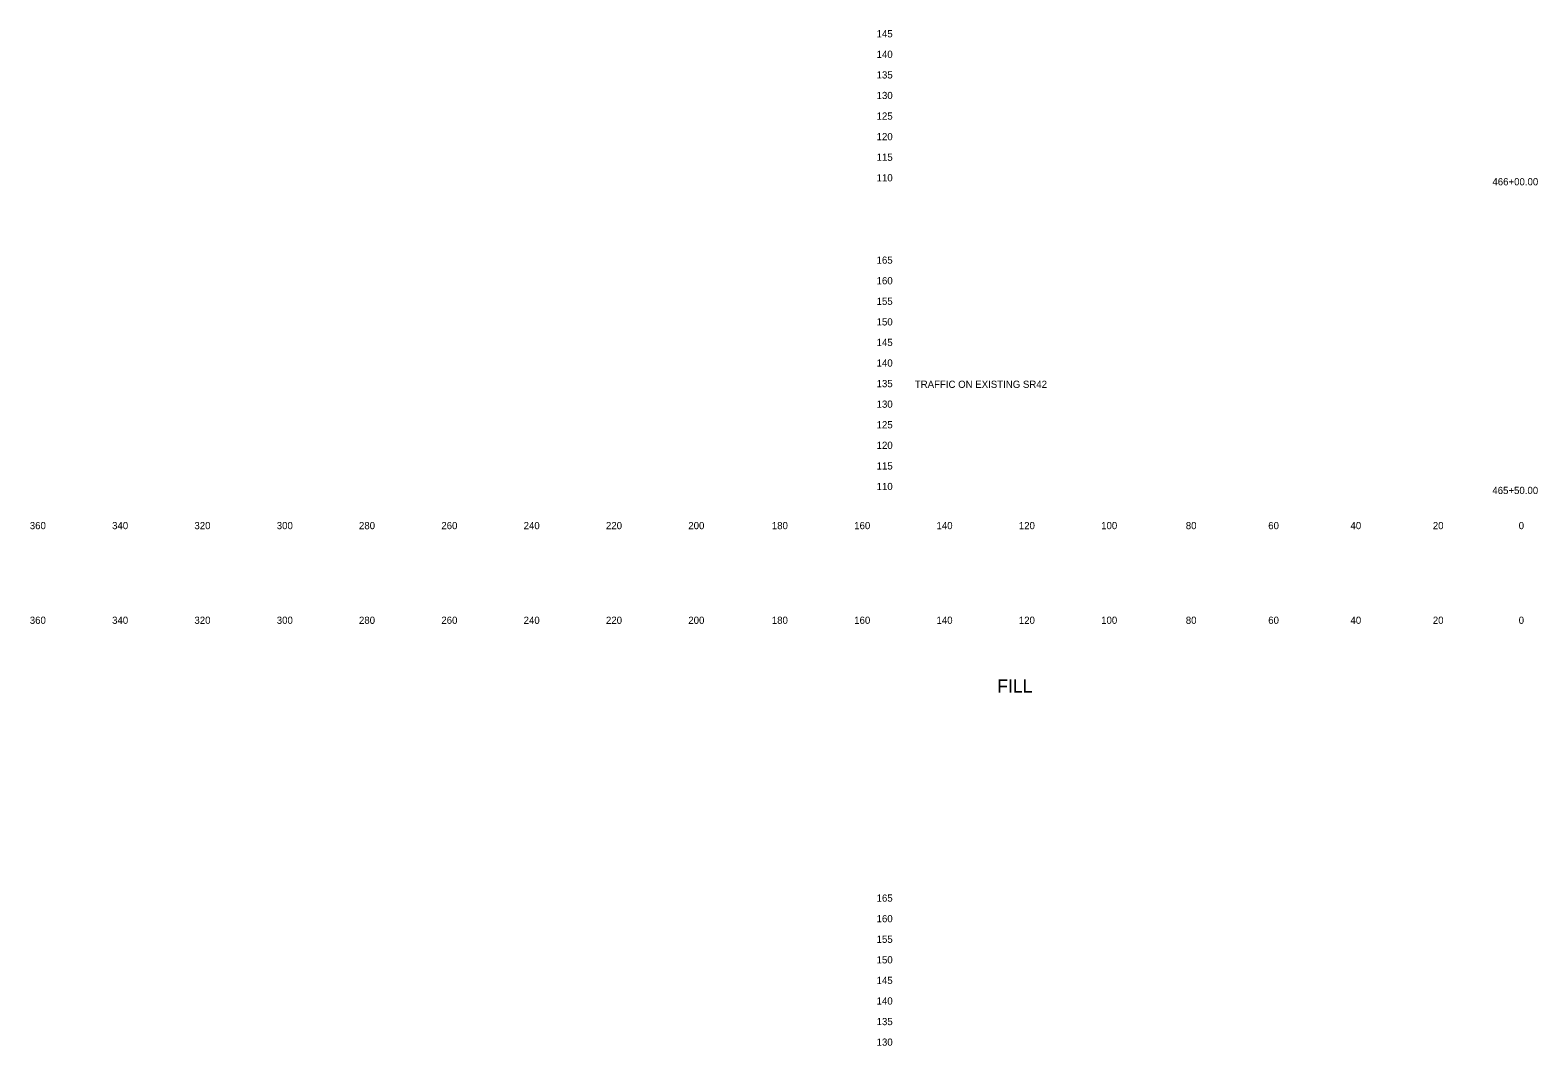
# Model space of a CAD drawing. Extents: x 21281 to 22024, y 6472 to 15198.
# Drawn here: x 21280.5 to 21646.8, y 8649.8 to 8896.6 of the extents above; entities that cross this region are included whole.
import ezdxf

# ---------------------------------------------------------------- set-up
doc = ezdxf.new("R2010")
doc.units = 0
for name, color, linetype in [('XS_SHEET_LABELS_ELEVATION', 7, 'Continuous'), ('XS_SHEET_LABELS_OFFSET', 7, 'Continuous'), ('XS_SHEET_LABELS_STATION', 7, 'Continuous')]:
    doc.layers.add(name, color=color, linetype=linetype)

msp = doc.modelspace()

# ---------------------------------------------------------------- texts
at = {"layer": 'XS_SHEET_LABELS_ELEVATION'}
for s, p in [('  145  ', (21484.84, 8894.84)), ('  140  ', (21484.84, 8889.84)), ('  135  ', (21484.84, 8884.84)), ('  130  ', (21484.84, 8879.84)), ('  125  ', (21484.84, 8874.84)), ('  120  ', (21484.84, 8869.84)), ('  115  ', (21484.84, 8864.84)), ('  110  ', (21484.84, 8859.84)), ('  165  ', (21484.84, 8839.84)), ('  160  ', (21484.84, 8834.84)), ('  155  ', (21484.84, 8829.84)), ('  150  ', (21484.84, 8824.84)), ('  145  ', (21484.84, 8819.84)), ('  140  ', (21484.84, 8814.84)), ('  135  ', (21484.84, 8809.84)), ('  130  ', (21484.84, 8804.84)), ('  125  ', (21484.84, 8799.84)), ('  120  ', (21484.84, 8794.84)), ('  115  ', (21484.84, 8789.84)), ('  110  ', (21484.84, 8784.84)), ('  165  ', (21484.84, 8684.84)), ('  160  ', (21484.84, 8679.84)), ('  155  ', (21484.84, 8674.84)), ('  150  ', (21484.84, 8669.84)), ('  145  ', (21484.84, 8664.84)), ('  140  ', (21484.84, 8659.84)), ('  135  ', (21484.84, 8654.84)), ('  130  ', (21484.84, 8649.84))]:
    msp.add_text(s, height=1.75, dxfattribs=at).set_placement(p)
at = {"layer": 'XS_SHEET_LABELS_OFFSET'}
for s, height, p in [('  360  ', 1.75, (21279.14, 8775.34)), ('  340  ', 1.75, (21299.13, 8775.34)), ('  320  ', 1.75, (21319.13, 8775.34)), ('  300  ', 1.75, (21339.13, 8775.34)), ('  280  ', 1.75, (21359.1, 8775.34)), ('  260  ', 1.75, (21379.11, 8775.34)), ('  240  ', 1.75, (21399.1, 8775.34)), ('  220  ', 1.75, (21419.1, 8775.34)), ('  200  ', 1.75, (21439.1, 8775.34)), ('  180  ', 1.75, (21459.39, 8775.34)), ('  160  ', 1.75, (21479.4, 8775.34)), ('  140  ', 1.75, (21499.39, 8775.34)), ('  120  ', 1.75, (21519.39, 8775.34)), ('  100  ', 1.75, (21539.39, 8775.34)), ('  80  ', 1.75, (21559.95, 8775.34)), ('  60  ', 1.75, (21579.97, 8775.34)), ('  40  ', 1.75, (21599.95, 8775.34)), ('  20  ', 1.75, (21619.95, 8775.34)), ('  0  ', 1.75, (21640.81, 8775.34)), ('  0  ', 1.75, (21640.81, 8775.34)), ('  360  ', 1.75, (21279.14, 8752.34)), ('  340  ', 1.75, (21299.13, 8752.34)), ('  320  ', 1.75, (21319.13, 8752.34)), ('  300  ', 1.75, (21339.13, 8752.34)), ('  280  ', 1.75, (21359.1, 8752.34)), ('  260  ', 1.75, (21379.11, 8752.34)), ('  240  ', 1.75, (21399.1, 8752.34)), ('  220  ', 1.75, (21419.1, 8752.34)), ('  200  ', 1.75, (21439.1, 8752.34)), ('  180  ', 1.75, (21459.39, 8752.34)), ('  160  ', 1.75, (21479.4, 8752.34)), ('  140  ', 1.75, (21499.39, 8752.34)), ('  120  ', 1.75, (21519.39, 8752.34)), ('  100  ', 1.75, (21539.39, 8752.34)), ('  80  ', 1.75, (21559.95, 8752.34)), ('  60  ', 1.75, (21579.97, 8752.34)), ('  40  ', 1.75, (21599.95, 8752.34)), ('  20  ', 1.75, (21619.95, 8752.34)), ('  0  ', 1.75, (21640.81, 8752.34)), ('  0  ', 1.75, (21640.81, 8752.34)), ('FILL', 3.222, (21515.4, 8735.63))]:
    msp.add_text(s, height=height, dxfattribs=at).set_placement(p)
at = {"layer": 'XS_SHEET_LABELS_STATION'}
for s, p in [('  466+00.00  ', (21634.43, 8858.89)), ('TRAFFIC ON EXISTING SR42', (21495.42, 8809.67)), ('  465+50.00  ', (21634.41, 8783.89))]:
    msp.add_text(s, height=1.75, dxfattribs=at).set_placement(p)

doc.saveas('drawing.dxf')
